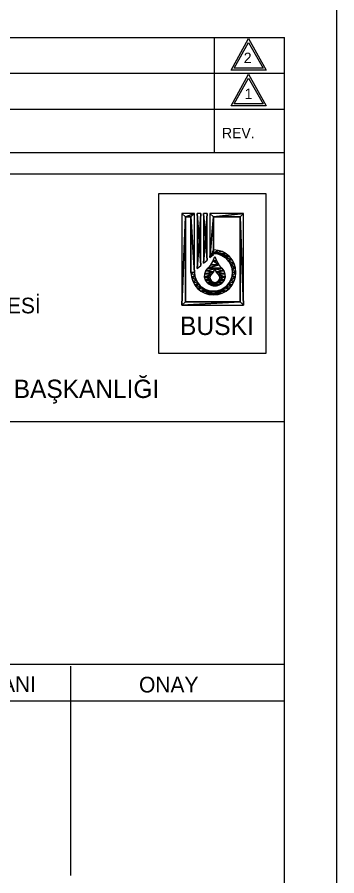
# Model space of a CAD drawing. Extents: x -10 to 1145, y -10 to 821.
# Drawn here: x 1083.8 to 1145, y 118.8 to 283.1 of the extents above; entities that cross this region are included whole.
import ezdxf

# ---------------------------------------------------------------- set-up
doc = ezdxf.new("R2010")
doc.units = 0
for name, color, linetype in [('Level 1', 7, 'Continuous'), ('Level 20', 7, 'Continuous'), ('Level 21', 7, 'Continuous'), ('Level 51', 7, 'Continuous'), ('Level 6', 7, 'Continuous'), ('Level 7', 7, 'Continuous'), ('Level 8', 7, 'Continuous')]:
    doc.layers.add(name, color=color, linetype=linetype)

msp = doc.modelspace()

# ---------------------------------------------------------------- linework, layer by layer
at = {"layer": 'Level 51'}
msp.add_lwpolyline([(-10, -10), (1145, -10), (1145, 821), (-10, 821)], close=True, dxfattribs=at)
at = {"layer": 'Level 6'}
for p, q in [((967.03, 279.24), (1135, 279.24)), ((967.03, 279.24), (1135, 279.24)), ((967.03, 279.24), (1135, 279.24)), ((967.03, 279.24), (1135, 279.24)), ((970.15, 279.24), (1131.87, 279.24)), ((970.15, 279.24), (1131.87, 279.24)), ((970.15, 279.24), (1131.87, 279.24)), ((970.15, 279.24), (1131.87, 279.24)), ((970.15, 279.24), (1131.87, 279.24)), ((970.15, 279.24), (1131.87, 279.24)), ((970.15, 279.24), (1131.87, 279.24)), ((970.15, 279.24), (1131.87, 279.24)), ((1121.62, 257.23), (1121.62, 279.24)), ((1121.62, 257.23), (1121.62, 279.24)), ((1121.62, 257.23), (1121.62, 279.24)), ((1121.62, 257.23), (1121.62, 279.24)), ((1135, 255.72), (1135, 279.24)), ((1135, 255.72), (1135, 279.24)), ((1135, 255.72), (1135, 279.24)), ((1135, 255.72), (1135, 279.24)), ((1135, 255.72), (1135, 279.24)), ((1135, 255.72), (1135, 279.24)), ((1135, 255.72), (1135, 279.24)), ((1135, 255.72), (1135, 279.24)), ((967.03, 272.38), (1135, 272.38)), ((967.03, 272.38), (1135, 272.38)), ((967.03, 272.38), (1135, 272.38)), ((967.03, 272.38), (1135, 272.38)), ((967.03, 265.52), (1135, 265.52)), ((967.03, 265.52), (1135, 265.52)), ((967.03, 265.52), (1135, 265.52)), ((967.03, 265.52), (1135, 265.52)), ((1135, 0), (1135, 262.93)), ((1135, 0), (1135, 262.93)), ((1135, 0), (1135, 262.93)), ((1135, 0), (1135, 262.93)), ((967.03, 257.23), (1135, 257.23)), ((967.03, 257.23), (1135, 257.23)), ((967.03, 257.23), (1135, 257.23)), ((967.03, 257.23), (1135, 257.23)), ((967.03, 253.14), (1135, 253.14)), ((967.03, 253.14), (1135, 253.14)), ((967.03, 253.14), (1135, 253.14)), ((967.03, 253.14), (1135, 253.14)), ((967.03, 205.73), (1135, 205.73)), ((967.03, 159.28), (1135, 159.28)), ((1094.09, 118.87), (1094.09, 158.88)), ((967.03, 152.28), (1135, 152.28))]:
    msp.add_line(p, q, dxfattribs=at)
at = {"layer": 'Level 7'}
for points in [[(1124.76, 273), (1128.13, 279.05), (1131.5, 273)], [(1124.76, 273), (1128.13, 279.05), (1131.5, 273)], [(1124.76, 273), (1128.13, 279.05), (1131.5, 273)], [(1124.76, 273), (1128.13, 279.05), (1131.5, 273)], [(1125.38, 273.37), (1128.13, 278.3), (1130.88, 273.37)], [(1125.38, 273.37), (1128.13, 278.3), (1130.88, 273.37)], [(1125.38, 273.37), (1128.13, 278.3), (1130.88, 273.37)], [(1125.38, 273.37), (1128.13, 278.3), (1130.88, 273.37)], [(1124.76, 266.14), (1128.13, 272.19), (1131.5, 266.14)], [(1124.76, 266.14), (1128.13, 272.19), (1131.5, 266.14)], [(1124.76, 266.14), (1128.13, 272.19), (1131.5, 266.14)], [(1124.76, 266.14), (1128.13, 272.19), (1131.5, 266.14)], [(1125.38, 266.51), (1128.13, 271.44), (1130.88, 266.51)], [(1125.38, 266.51), (1128.13, 271.44), (1130.88, 266.51)], [(1125.38, 266.51), (1128.13, 271.44), (1130.88, 266.51)], [(1125.38, 266.51), (1128.13, 271.44), (1130.88, 266.51)]]:
    msp.add_lwpolyline(points, close=True, dxfattribs=at)
at = {"layer": 'Level 8'}
for points in [[(1110.92, 249.39), (1131.43, 249.39), (1131.43, 218.78), (1110.92, 218.78)], [(1115.36, 245.56), (1115.36, 227.97), (1116.04, 244.88)], [(1116.04, 244.88), (1117.78, 245.56), (1115.36, 245.56)], [(1115.36, 245.56), (1115.36, 227.97), (1116.04, 244.88)], [(1116.04, 244.88), (1117.78, 245.56), (1115.36, 245.56)], [(1116.04, 244.88), (1115.36, 227.97), (1116.04, 228.65)], [(1116.04, 244.88), (1115.36, 227.97), (1116.04, 228.65)], [(1117.78, 245.56), (1116.04, 244.88), (1117.09, 244.88)], [(1117.78, 245.56), (1116.04, 244.88), (1117.09, 244.88)], [(1117.78, 245.56), (1117.09, 244.88), (1117.78, 234.27)], [(1117.78, 245.56), (1117.09, 244.88), (1117.78, 234.27)], [(1117.09, 244.88), (1117.09, 234.27), (1117.78, 234.27)], [(1117.09, 244.88), (1117.09, 234.27), (1117.78, 234.27)], [(1118.64, 240.28), (1118.98, 245.56), (1118.3, 245.56)], [(1118.64, 240.28), (1118.3, 245.56), (1118.3, 235)], [(1118.64, 240.28), (1118.98, 245.56), (1118.3, 245.56)], [(1118.64, 240.28), (1118.3, 245.56), (1118.3, 235)], [(1118.64, 240.28), (1118.98, 235.58), (1118.98, 245.56)], [(1118.64, 240.28), (1118.98, 235.58), (1118.98, 245.56)], [(1119.85, 240.81), (1120.19, 245.56), (1119.51, 245.56)], [(1119.85, 240.81), (1119.51, 245.56), (1119.51, 236.06)], [(1119.85, 240.81), (1120.19, 245.56), (1119.51, 245.56)], [(1119.85, 240.81), (1119.51, 245.56), (1119.51, 236.06)], [(1119.85, 240.81), (1120.19, 236.63), (1120.19, 245.56)], [(1119.85, 240.81), (1120.19, 236.63), (1120.19, 245.56)], [(1120.72, 245.56), (1120.72, 237.1), (1121.4, 244.88)], [(1121.4, 244.88), (1127.17, 245.56), (1120.72, 245.56)], [(1120.72, 245.56), (1120.72, 237.1), (1121.4, 244.88)], [(1121.4, 244.88), (1127.17, 245.56), (1120.72, 245.56)], [(1121.4, 244.88), (1120.72, 237.1), (1121.4, 238.58)], [(1121.4, 244.88), (1120.72, 237.1), (1121.4, 238.58)], [(1127.17, 245.56), (1121.4, 244.88), (1126.49, 244.88)], [(1127.17, 245.56), (1121.4, 244.88), (1126.49, 244.88)], [(1127.17, 245.56), (1126.49, 244.88), (1127.17, 227.97)], [(1127.17, 245.56), (1126.49, 244.88), (1127.17, 227.97)], [(1126.49, 244.88), (1126.49, 228.65), (1127.17, 227.97)], [(1126.49, 244.88), (1126.49, 228.65), (1127.17, 227.97)], [(1118.64, 240.28), (1118.3, 235), (1118.98, 235.58)], [(1118.64, 240.28), (1118.3, 235), (1118.98, 235.58)], [(1119.85, 240.81), (1119.51, 236.06), (1120.19, 236.63)], [(1119.85, 240.81), (1119.51, 236.06), (1120.19, 236.63)], [(1121.4, 238.58), (1120.72, 237.1), (1121.4, 237.89)], [(1121.4, 238.58), (1120.72, 237.1), (1121.4, 237.89)], [(1121.4, 238.58), (1121.4, 237.89), (1122.24, 238.49)], [(1121.4, 238.58), (1121.4, 237.89), (1122.24, 238.49)], [(1122.24, 238.49), (1121.4, 237.89), (1123.05, 238.25)], [(1122.24, 238.49), (1121.4, 237.89), (1123.05, 238.25)], [(1121.4, 237.89), (1120.72, 237.1), (1121.4, 237.68)], [(1121.4, 237.89), (1120.72, 237.1), (1121.4, 237.68)], [(1121.66, 237.32), (1121.99, 236.49), (1121.34, 236.49)], [(1121.66, 237.32), (1121.99, 236.49), (1121.34, 236.49)], [(1123.05, 238.25), (1121.4, 237.89), (1123.79, 237.85)], [(1123.05, 238.25), (1121.4, 237.89), (1123.79, 237.85)], [(1121.4, 237.89), (1122.2, 237.8), (1123.79, 237.85)], [(1121.4, 237.89), (1122.2, 237.8), (1123.79, 237.85)], [(1123.79, 237.85), (1122.2, 237.8), (1124.44, 237.31)], [(1123.79, 237.85), (1122.2, 237.8), (1124.44, 237.31)], [(1122.2, 237.8), (1122.97, 237.53), (1124.44, 237.31)], [(1122.2, 237.8), (1122.97, 237.53), (1124.44, 237.31)], [(1122.97, 237.53), (1123.66, 237.1), (1124.44, 237.31)], [(1122.97, 237.53), (1123.66, 237.1), (1124.44, 237.31)], [(1124.44, 237.31), (1123.66, 237.1), (1124.98, 236.66)], [(1124.44, 237.31), (1123.66, 237.1), (1124.98, 236.66)], [(1123.66, 237.1), (1124.23, 236.53), (1124.98, 236.66)], [(1123.66, 237.1), (1124.23, 236.53), (1124.98, 236.66)], [(1124.98, 236.66), (1124.23, 236.53), (1125.38, 235.92)], [(1124.98, 236.66), (1124.23, 236.53), (1125.38, 235.92)], [(1120.3, 235.06), (1121.66, 234.95), (1119.92, 234.56)], [(1120.3, 235.06), (1121.66, 234.95), (1119.92, 234.56)], [(1122.45, 235.73), (1123.03, 235.06), (1120.3, 235.06)], [(1120.88, 235.73), (1122.45, 235.73), (1120.3, 235.06)], [(1122.45, 235.73), (1123.03, 235.06), (1120.3, 235.06)], [(1120.88, 235.73), (1122.45, 235.73), (1120.3, 235.06)], [(1123.03, 235.06), (1121.66, 234.95), (1120.3, 235.06)], [(1123.03, 235.06), (1121.66, 234.95), (1120.3, 235.06)], [(1121.34, 236.49), (1122.45, 235.73), (1120.88, 235.73)], [(1121.34, 236.49), (1122.45, 235.73), (1120.88, 235.73)], [(1121.99, 236.49), (1122.45, 235.73), (1121.34, 236.49)], [(1121.99, 236.49), (1122.45, 235.73), (1121.34, 236.49)], [(1123.03, 235.06), (1123.4, 234.56), (1121.66, 234.95)], [(1123.03, 235.06), (1123.4, 234.56), (1121.66, 234.95)], [(1124.23, 236.53), (1124.66, 235.84), (1125.38, 235.92)], [(1124.23, 236.53), (1124.66, 235.84), (1125.38, 235.92)], [(1125.38, 235.92), (1124.66, 235.84), (1125.62, 235.11)], [(1125.38, 235.92), (1124.66, 235.84), (1125.62, 235.11)], [(1124.66, 235.84), (1124.93, 235.08), (1125.62, 235.11)], [(1124.66, 235.84), (1124.93, 235.08), (1125.62, 235.11)], [(1125.62, 235.11), (1124.93, 235.08), (1125.7, 234.27)], [(1125.62, 235.11), (1124.93, 235.08), (1125.7, 234.27)], [(1124.93, 235.08), (1125.02, 234.27), (1125.7, 234.27)], [(1124.93, 235.08), (1125.02, 234.27), (1125.7, 234.27)], [(1117.09, 234.27), (1117.18, 233.43), (1117.87, 233.46)], [(1117.78, 234.27), (1117.09, 234.27), (1117.87, 233.46)], [(1117.09, 234.27), (1117.18, 233.43), (1117.87, 233.46)], [(1117.78, 234.27), (1117.09, 234.27), (1117.87, 233.46)], [(1117.87, 233.46), (1117.18, 233.43), (1118.13, 232.7)], [(1117.87, 233.46), (1117.18, 233.43), (1118.13, 232.7)], [(1117.18, 233.43), (1117.42, 232.62), (1118.13, 232.7)], [(1117.18, 233.43), (1117.42, 232.62), (1118.13, 232.7)], [(1119.72, 233.97), (1121.03, 233.95), (1119.71, 233.35)], [(1119.72, 233.97), (1121.03, 233.95), (1119.71, 233.35)], [(1121.03, 233.95), (1120.82, 233.66), (1119.71, 233.35)], [(1121.03, 233.95), (1120.82, 233.66), (1119.71, 233.35)], [(1120.82, 233.66), (1120.73, 233.3), (1119.71, 233.35)], [(1120.82, 233.66), (1120.73, 233.3), (1119.71, 233.35)], [(1119.92, 234.56), (1121.42, 234.41), (1119.72, 233.97)], [(1119.92, 234.56), (1121.42, 234.41), (1119.72, 233.97)], [(1121.42, 234.41), (1121.03, 233.95), (1119.72, 233.97)], [(1121.42, 234.41), (1121.03, 233.95), (1119.72, 233.97)], [(1121.66, 234.95), (1121.42, 234.41), (1119.92, 234.56)], [(1121.66, 234.95), (1121.42, 234.41), (1119.92, 234.56)], [(1121.66, 234.95), (1123.4, 234.56), (1121.9, 234.41)], [(1121.66, 234.95), (1123.4, 234.56), (1121.9, 234.41)], [(1123.4, 234.56), (1123.6, 233.97), (1121.9, 234.41)], [(1123.4, 234.56), (1123.6, 233.97), (1121.9, 234.41)], [(1121.9, 234.41), (1123.6, 233.97), (1122.29, 233.95)], [(1121.9, 234.41), (1123.6, 233.97), (1122.29, 233.95)], [(1123.6, 233.97), (1123.61, 233.35), (1122.29, 233.95)], [(1123.6, 233.97), (1123.61, 233.35), (1122.29, 233.95)], [(1122.29, 233.95), (1123.61, 233.35), (1122.51, 233.66)], [(1122.29, 233.95), (1123.61, 233.35), (1122.51, 233.66)], [(1122.51, 233.66), (1123.61, 233.35), (1122.59, 233.3)], [(1122.51, 233.66), (1123.61, 233.35), (1122.59, 233.3)], [(1124.93, 233.46), (1124.66, 232.7), (1125.62, 233.43)], [(1124.93, 233.46), (1124.66, 232.7), (1125.62, 233.43)], [(1125.62, 233.43), (1124.66, 232.7), (1125.38, 232.62)], [(1125.62, 233.43), (1124.66, 232.7), (1125.38, 232.62)], [(1125.7, 234.27), (1124.93, 233.46), (1125.62, 233.43)], [(1125.02, 234.27), (1124.93, 233.46), (1125.7, 234.27)], [(1125.7, 234.27), (1124.93, 233.46), (1125.62, 233.43)], [(1125.02, 234.27), (1124.93, 233.46), (1125.7, 234.27)], [(1118.13, 232.7), (1117.42, 232.62), (1118.57, 232.01)], [(1118.13, 232.7), (1117.42, 232.62), (1118.57, 232.01)], [(1117.42, 232.62), (1117.82, 231.88), (1118.57, 232.01)], [(1117.42, 232.62), (1117.82, 231.88), (1118.57, 232.01)], [(1118.57, 232.01), (1117.82, 231.88), (1119.14, 231.44)], [(1118.57, 232.01), (1117.82, 231.88), (1119.14, 231.44)], [(1117.82, 231.88), (1118.36, 231.23), (1119.14, 231.44)], [(1117.82, 231.88), (1118.36, 231.23), (1119.14, 231.44)], [(1119.71, 233.35), (1120.73, 233.3), (1119.9, 232.76)], [(1119.71, 233.35), (1120.73, 233.3), (1119.9, 232.76)], [(1120.73, 233.3), (1120.8, 232.93), (1119.9, 232.76)], [(1120.73, 233.3), (1120.8, 232.93), (1119.9, 232.76)], [(1120.8, 232.93), (1121, 232.62), (1119.9, 232.76)], [(1120.8, 232.93), (1121, 232.62), (1119.9, 232.76)], [(1119.9, 232.76), (1121, 232.62), (1120.26, 232.26)], [(1119.9, 232.76), (1121, 232.62), (1120.26, 232.26)], [(1121, 232.62), (1121.3, 232.42), (1120.26, 232.26)], [(1121, 232.62), (1121.3, 232.42), (1120.26, 232.26)], [(1121.3, 232.42), (1121.66, 232.34), (1120.26, 232.26)], [(1121.3, 232.42), (1121.66, 232.34), (1120.26, 232.26)], [(1121.66, 232.34), (1123.06, 232.26), (1120.26, 232.26)], [(1121.66, 232.34), (1123.06, 232.26), (1120.26, 232.26)], [(1120.26, 232.26), (1122.56, 231.89), (1120.76, 231.89)], [(1123.06, 232.26), (1122.56, 231.89), (1120.26, 232.26)], [(1120.26, 232.26), (1122.56, 231.89), (1120.76, 231.89)], [(1123.06, 232.26), (1122.56, 231.89), (1120.26, 232.26)], [(1120.76, 231.89), (1121.97, 231.7), (1121.35, 231.7)], [(1122.56, 231.89), (1121.97, 231.7), (1120.76, 231.89)], [(1120.76, 231.89), (1121.97, 231.7), (1121.35, 231.7)], [(1122.56, 231.89), (1121.97, 231.7), (1120.76, 231.89)], [(1122.02, 232.42), (1123.06, 232.26), (1121.66, 232.34)], [(1122.02, 232.42), (1123.06, 232.26), (1121.66, 232.34)], [(1122.33, 232.62), (1123.06, 232.26), (1122.02, 232.42)], [(1122.33, 232.62), (1123.06, 232.26), (1122.02, 232.42)], [(1122.53, 232.93), (1123.42, 232.76), (1122.33, 232.62)], [(1122.53, 232.93), (1123.42, 232.76), (1122.33, 232.62)], [(1123.42, 232.76), (1123.06, 232.26), (1122.33, 232.62)], [(1123.42, 232.76), (1123.06, 232.26), (1122.33, 232.62)], [(1122.59, 233.3), (1123.42, 232.76), (1122.53, 232.93)], [(1122.59, 233.3), (1123.42, 232.76), (1122.53, 232.93)], [(1123.61, 233.35), (1123.42, 232.76), (1122.59, 233.3)], [(1123.61, 233.35), (1123.42, 232.76), (1122.59, 233.3)], [(1124.23, 232.01), (1123.66, 231.44), (1124.98, 231.88)], [(1124.23, 232.01), (1123.66, 231.44), (1124.98, 231.88)], [(1124.98, 231.88), (1123.66, 231.44), (1124.44, 231.23)], [(1124.98, 231.88), (1123.66, 231.44), (1124.44, 231.23)], [(1124.66, 232.7), (1124.23, 232.01), (1125.38, 232.62)], [(1124.66, 232.7), (1124.23, 232.01), (1125.38, 232.62)], [(1125.38, 232.62), (1124.23, 232.01), (1124.98, 231.88)], [(1125.38, 232.62), (1124.23, 232.01), (1124.98, 231.88)], [(1119.14, 231.44), (1118.36, 231.23), (1119.83, 231)], [(1119.14, 231.44), (1118.36, 231.23), (1119.83, 231)], [(1118.36, 231.23), (1119.01, 230.69), (1119.83, 231)], [(1118.36, 231.23), (1119.01, 230.69), (1119.83, 231)], [(1119.83, 231), (1119.01, 230.69), (1120.59, 230.74)], [(1119.83, 231), (1119.01, 230.69), (1120.59, 230.74)], [(1120.59, 230.74), (1119.01, 230.69), (1121.4, 230.65)], [(1120.59, 230.74), (1119.01, 230.69), (1121.4, 230.65)], [(1119.01, 230.69), (1119.75, 230.29), (1121.4, 230.65)], [(1119.01, 230.69), (1119.75, 230.29), (1121.4, 230.65)], [(1121.4, 230.65), (1119.75, 230.29), (1123.05, 230.29)], [(1121.4, 230.65), (1119.75, 230.29), (1123.05, 230.29)], [(1119.75, 230.29), (1120.56, 230.05), (1122.24, 230.05)], [(1123.05, 230.29), (1119.75, 230.29), (1122.24, 230.05)], [(1119.75, 230.29), (1120.56, 230.05), (1122.24, 230.05)], [(1123.05, 230.29), (1119.75, 230.29), (1122.24, 230.05)], [(1122.2, 230.74), (1121.4, 230.65), (1123.79, 230.69)], [(1122.2, 230.74), (1121.4, 230.65), (1123.79, 230.69)], [(1123.79, 230.69), (1121.4, 230.65), (1123.05, 230.29)], [(1123.79, 230.69), (1121.4, 230.65), (1123.05, 230.29)], [(1122.97, 231), (1122.2, 230.74), (1123.79, 230.69)], [(1122.97, 231), (1122.2, 230.74), (1123.79, 230.69)], [(1123.66, 231.44), (1122.97, 231), (1124.44, 231.23)], [(1123.66, 231.44), (1122.97, 231), (1124.44, 231.23)], [(1124.44, 231.23), (1122.97, 231), (1123.79, 230.69)], [(1124.44, 231.23), (1122.97, 231), (1123.79, 230.69)], [(1126.49, 228.65), (1115.36, 227.97), (1127.17, 227.97)], [(1115.36, 227.97), (1126.49, 228.65), (1116.04, 228.65)], [(1126.49, 228.65), (1115.36, 227.97), (1127.17, 227.97)], [(1115.36, 227.97), (1126.49, 228.65), (1116.04, 228.65)], [(1122.24, 230.05), (1120.56, 230.05), (1121.4, 229.96)], [(1122.24, 230.05), (1120.56, 230.05), (1121.4, 229.96)]]:
    msp.add_lwpolyline(points, close=True, dxfattribs=at)
for points in [[(1117.78, 234.27), (1117.78, 234.27), (1117.78, 245.56), (1115.36, 245.56), (1115.36, 227.97), (1127.17, 227.97), (1127.17, 245.56), (1120.72, 245.56), (1120.72, 237.1), (1121.4, 237.68), (1121.4, 237.89)], [(1117.78, 234.27), (1117.78, 234.27), (1117.78, 245.56), (1115.36, 245.56), (1115.36, 227.97), (1127.17, 227.97), (1127.17, 245.56), (1120.72, 245.56), (1120.72, 237.1), (1121.4, 237.68), (1121.4, 237.89)], [(1117.09, 234.27), (1117.09, 234.27), (1117.09, 244.88), (1116.04, 244.88), (1116.04, 228.65), (1126.49, 228.65), (1126.49, 244.88), (1121.4, 244.88), (1121.4, 238.58)], [(1117.09, 234.27), (1117.09, 234.27), (1117.09, 244.88), (1116.04, 244.88), (1116.04, 228.65), (1126.49, 228.65), (1126.49, 244.88), (1121.4, 244.88), (1121.4, 238.58)], [(1118.98, 245.56), (1118.3, 245.56), (1118.3, 235), (1118.98, 235.58), (1118.98, 245.56)], [(1118.98, 245.56), (1118.3, 245.56), (1118.3, 235), (1118.98, 235.58), (1118.98, 245.56)], [(1119.51, 236.06), (1120.19, 236.63), (1120.19, 245.56), (1119.51, 245.56), (1119.51, 236.06)], [(1119.51, 236.06), (1120.19, 236.63), (1120.19, 245.56), (1119.51, 245.56), (1119.51, 236.06)], [(1121.4, 238.58), (1121.4, 238.57)], [(1121.4, 238.58), (1121.4, 238.57)], [(1121.4, 237.89), (1121.4, 237.89)], [(1121.4, 237.89), (1121.4, 237.89)]]:
    msp.add_lwpolyline(points, dxfattribs=at)
for centre, radius, start, end in [((1121.4, 234.27), 4.31, 180, 90), ((1121.4, 234.27), 4.31, 180, 90), ((1121.4, 234.27), 3.62, 180, 90), ((1121.4, 234.27), 3.62, 180, 90), ((1116.63, 238.81), 5.25, 314.2894, 343.392), ((1116.63, 238.81), 5.25, 314.2894, 343.392), ((1126.69, 238.81), 5.25, 196.608, 225.7106), ((1126.69, 238.81), 5.25, 196.608, 225.7106), ((1121.66, 233.64), 1.97, 133.9191, 46.0809), ((1121.66, 233.64), 1.97, 133.9191, 46.0809), ((1121.66, 233.27), 0.929, 132.7094, 47.2906), ((1121.66, 233.27), 0.929, 132.7094, 47.2906), ((1119.64, 235.53), 2.1, 311.4103, 344.0384), ((1119.64, 235.53), 2.1, 311.4103, 344.0384), ((1123.68, 235.53), 2.1, 195.9616, 228.5897), ((1123.68, 235.53), 2.1, 195.9616, 228.5897)]:
    msp.add_arc(centre, radius, start, end, dxfattribs=at)

# ---------------------------------------------------------------- texts
at = {"layer": 'Level 1'}
for s, p in [('2', (1127.2, 274.33)), ('1', (1127.37, 267.46))]:
    msp.add_text(s, height=2, dxfattribs=at).set_placement(p)
at = {"layer": 'Level 20'}
msp.add_text('PLANLAMA YATIRIM VE İNŞAAT DAİRE BAŞKANLIĞI', height=3.5, dxfattribs=at).set_placement((995.28, 210.24))
at = {"layer": 'Level 21'}
msp.add_text('BUSKI', height=3.534, dxfattribs=at).set_placement((1114.97, 222.29))
msp.add_text('BUSKI', height=3.534, dxfattribs=at).set_placement((1114.97, 222.29))
at = {"layer": 'Level 7'}
for s, height, p in [('REV.', 2, (1123.03, 259.94)), ('BURSA SU VE KANALİZASYON İDARESİ', 3, (1012.33, 226.43)), ('DAİRE BAŞKANI', 3, (1056.68, 153.98)), ('ONAY', 3, (1107.16, 153.87))]:
    msp.add_text(s, height=height, dxfattribs=at).set_placement(p)

doc.saveas('drawing.dxf')
